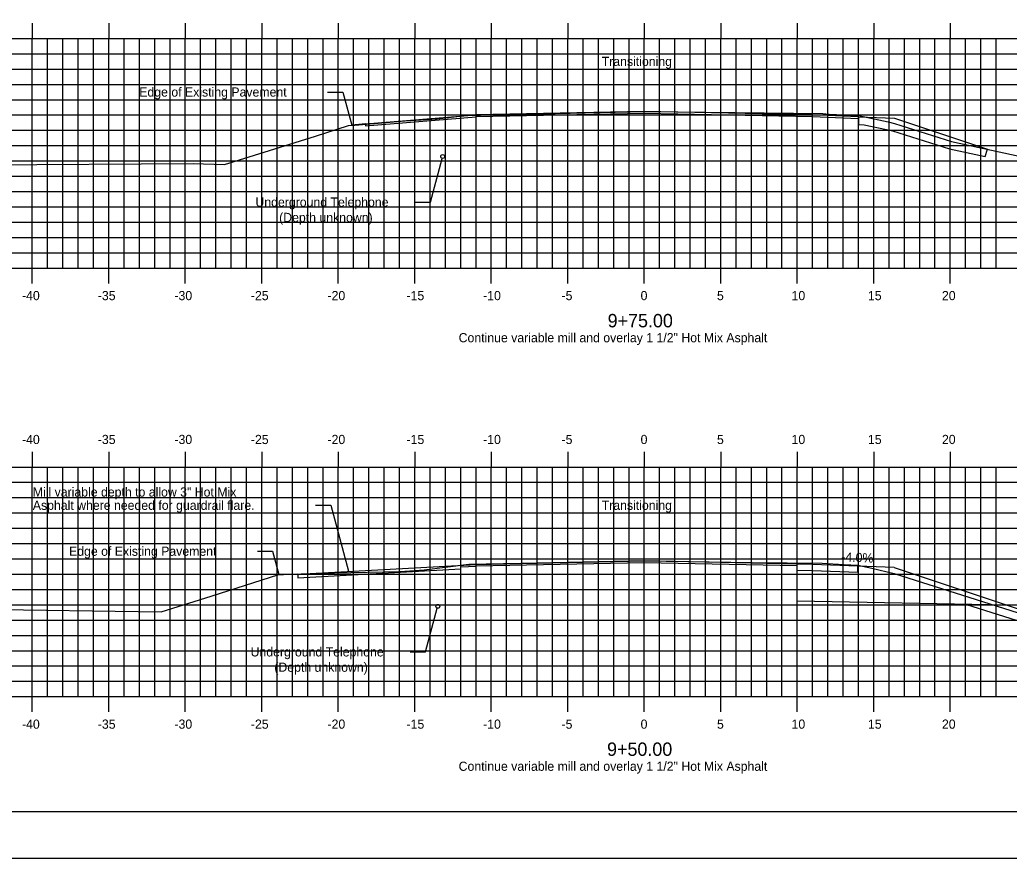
# Model space of a CAD drawing. Extents: x 2194738 to 2195190, y 863888 to 863998.
# Drawn here: x 2194879.4 to 2194944.1, y 863888.4 to 863943.2 of the extents above; entities that cross this region are included whole.
import ezdxf

# ---------------------------------------------------------------- set-up
doc = ezdxf.new("R2010")
doc.units = 0
for name, color, linetype in [('ANNOTATION', 7, 'Continuous'), ('BORDER', 7, 'Continuous'), ('H_V ANNOTATION', 7, 'Continuous'), ('MAJOR', 7, 'Continuous'), ('MINOR', 7, 'Continuous'), ('PLOT BOUNDARY', 7, 'Continuous'), ('S_Roadway_Centerline', 7, 'Continuous'), ('S_Utilities_Pole_Power', 7, 'Continuous'), ('TEMPLATE', 7, 'Continuous')]:
    doc.layers.add(name, color=color, linetype=linetype)

msp = doc.modelspace()

# ---------------------------------------------------------------- linework, layer by layer
at = {"layer": 'ANNOTATION'}
for points in [[(2194899.551, 863938.446), (2194900.551, 863938.446), (2194900.551, 863938.446), (2194901.131, 863936.283)], [(2194905.279, 863931.255), (2194906.279, 863931.255), (2194907.043, 863934.109)], [(2194898.768, 863911.446), (2194899.768, 863911.446), (2194900.923, 863907.133)], [(2194894.964, 863908.446), (2194895.964, 863908.446), (2194895.964, 863908.446), (2194896.37, 863906.93)], [(2194904.963, 863901.869), (2194905.963, 863901.869), (2194906.727, 863904.723)]]:
    msp.add_lwpolyline(points, dxfattribs=at)
at = {"layer": 'BORDER'}
msp.add_lwpolyline([(2194845.256, 863891.446), (2195005.256, 863891.446), (2195005.256, 863996.446), (2194845.256, 863996.446)], close=True, dxfattribs=at)
at = {"layer": 'MAJOR'}
for p, q in [((2194880.256, 863942.948), (2194880.256, 863941.946)), ((2194885.256, 863942.948), (2194885.256, 863941.946)), ((2194890.256, 863942.948), (2194890.256, 863941.946)), ((2194895.256, 863942.948), (2194895.256, 863941.946)), ((2194900.256, 863942.948), (2194900.256, 863941.946)), ((2194905.256, 863942.948), (2194905.256, 863941.946)), ((2194910.256, 863942.948), (2194910.256, 863941.946)), ((2194915.256, 863942.948), (2194915.256, 863941.946)), ((2194920.256, 863942.948), (2194920.256, 863941.946)), ((2194925.256, 863942.948), (2194925.256, 863941.946)), ((2194930.256, 863942.948), (2194930.256, 863941.946)), ((2194935.256, 863942.948), (2194935.256, 863941.946)), ((2194940.256, 863942.948), (2194940.256, 863941.946)), ((2194850.256, 863941.946), (2194990.256, 863941.946)), ((2194880.256, 863926.946), (2194880.256, 863941.946)), ((2194885.256, 863926.946), (2194885.256, 863941.946)), ((2194890.256, 863926.946), (2194890.256, 863941.946)), ((2194895.256, 863926.946), (2194895.256, 863941.946)), ((2194900.256, 863926.946), (2194900.256, 863941.946)), ((2194905.256, 863926.946), (2194905.256, 863941.946)), ((2194910.256, 863926.946), (2194910.256, 863941.946)), ((2194915.256, 863926.946), (2194915.256, 863941.946)), ((2194920.256, 863926.946), (2194920.256, 863941.946)), ((2194925.256, 863926.946), (2194925.256, 863941.946)), ((2194930.256, 863926.946), (2194930.256, 863941.946)), ((2194935.256, 863926.946), (2194935.256, 863941.946)), ((2194940.256, 863926.946), (2194940.256, 863941.946)), ((2194850.256, 863936.946), (2194990.256, 863936.946)), ((2194850.256, 863931.946), (2194990.256, 863931.946)), ((2194850.256, 863926.946), (2194990.256, 863926.946)), ((2194880.256, 863925.944), (2194880.256, 863926.946)), ((2194885.256, 863925.944), (2194885.256, 863926.946)), ((2194890.256, 863925.944), (2194890.256, 863926.946)), ((2194895.256, 863925.944), (2194895.256, 863926.946)), ((2194900.256, 863925.944), (2194900.256, 863926.946)), ((2194905.256, 863925.944), (2194905.256, 863926.946)), ((2194910.256, 863925.944), (2194910.256, 863926.946)), ((2194915.256, 863925.944), (2194915.256, 863926.946)), ((2194920.256, 863925.944), (2194920.256, 863926.946)), ((2194925.256, 863925.944), (2194925.256, 863926.946)), ((2194930.256, 863925.944), (2194930.256, 863926.946)), ((2194935.256, 863925.944), (2194935.256, 863926.946)), ((2194940.256, 863925.944), (2194940.256, 863926.946)), ((2194880.256, 863914.948), (2194880.256, 863913.946)), ((2194885.256, 863914.948), (2194885.256, 863913.946)), ((2194890.256, 863914.948), (2194890.256, 863913.946)), ((2194895.256, 863914.948), (2194895.256, 863913.946)), ((2194900.256, 863914.948), (2194900.256, 863913.946)), ((2194905.256, 863914.948), (2194905.256, 863913.946)), ((2194910.256, 863914.948), (2194910.256, 863913.946)), ((2194915.256, 863914.948), (2194915.256, 863913.946)), ((2194920.256, 863914.948), (2194920.256, 863913.946)), ((2194925.256, 863914.948), (2194925.256, 863913.946)), ((2194930.256, 863914.948), (2194930.256, 863913.946)), ((2194935.256, 863914.948), (2194935.256, 863913.946)), ((2194940.256, 863914.948), (2194940.256, 863913.946)), ((2194850.256, 863913.946), (2194990.256, 863913.946)), ((2194850.256, 863913.946), (2194990.256, 863913.946)), ((2194880.256, 863898.946), (2194880.256, 863913.946)), ((2194885.256, 863898.946), (2194885.256, 863913.946)), ((2194890.256, 863898.946), (2194890.256, 863913.946)), ((2194895.256, 863898.946), (2194895.256, 863913.946)), ((2194900.256, 863898.946), (2194900.256, 863913.946)), ((2194905.256, 863898.946), (2194905.256, 863913.946)), ((2194910.256, 863898.946), (2194910.256, 863913.946)), ((2194915.256, 863898.946), (2194915.256, 863913.946)), ((2194920.256, 863898.946), (2194920.256, 863913.946)), ((2194925.256, 863898.946), (2194925.256, 863913.946)), ((2194930.256, 863898.946), (2194930.256, 863913.946)), ((2194935.256, 863898.946), (2194935.256, 863913.946)), ((2194940.256, 863898.946), (2194940.256, 863913.946)), ((2194850.256, 863908.946), (2194990.256, 863908.946)), ((2194850.256, 863903.946), (2194990.256, 863903.946)), ((2194850.256, 863898.946), (2194990.256, 863898.946)), ((2194880.256, 863897.944), (2194880.256, 863898.946)), ((2194885.256, 863897.944), (2194885.256, 863898.946)), ((2194890.256, 863897.944), (2194890.256, 863898.946)), ((2194895.256, 863897.944), (2194895.256, 863898.946)), ((2194900.256, 863897.944), (2194900.256, 863898.946)), ((2194905.256, 863897.944), (2194905.256, 863898.946)), ((2194910.256, 863897.944), (2194910.256, 863898.946)), ((2194915.256, 863897.944), (2194915.256, 863898.946)), ((2194920.256, 863897.944), (2194920.256, 863898.946)), ((2194925.256, 863897.944), (2194925.256, 863898.946)), ((2194930.256, 863897.944), (2194930.256, 863898.946)), ((2194935.256, 863897.944), (2194935.256, 863898.946)), ((2194940.256, 863897.944), (2194940.256, 863898.946))]:
    msp.add_line(p, q, dxfattribs=at)
at = {"layer": 'MINOR'}
for p, q in [((2194881.256, 863926.946), (2194881.256, 863941.946)), ((2194882.256, 863926.946), (2194882.256, 863941.946)), ((2194883.256, 863926.946), (2194883.256, 863941.946)), ((2194884.256, 863926.946), (2194884.256, 863941.946)), ((2194886.256, 863926.946), (2194886.256, 863941.946)), ((2194887.256, 863926.946), (2194887.256, 863941.946)), ((2194888.256, 863926.946), (2194888.256, 863941.946)), ((2194889.256, 863926.946), (2194889.256, 863941.946)), ((2194891.256, 863926.946), (2194891.256, 863941.946)), ((2194892.256, 863926.946), (2194892.256, 863941.946)), ((2194893.256, 863926.946), (2194893.256, 863941.946)), ((2194894.256, 863926.946), (2194894.256, 863941.946)), ((2194896.256, 863926.946), (2194896.256, 863941.946)), ((2194897.256, 863926.946), (2194897.256, 863941.946)), ((2194898.256, 863926.946), (2194898.256, 863941.946)), ((2194899.256, 863926.946), (2194899.256, 863941.946)), ((2194901.256, 863926.946), (2194901.256, 863941.946)), ((2194902.256, 863926.946), (2194902.256, 863941.946)), ((2194903.256, 863926.946), (2194903.256, 863941.946)), ((2194904.256, 863926.946), (2194904.256, 863941.946)), ((2194906.256, 863926.946), (2194906.256, 863941.946)), ((2194907.256, 863926.946), (2194907.256, 863941.946)), ((2194908.256, 863926.946), (2194908.256, 863941.946)), ((2194909.256, 863926.946), (2194909.256, 863941.946)), ((2194911.256, 863926.946), (2194911.256, 863941.946)), ((2194912.256, 863926.946), (2194912.256, 863941.946)), ((2194913.256, 863926.946), (2194913.256, 863941.946)), ((2194914.256, 863926.946), (2194914.256, 863941.946)), ((2194916.256, 863926.946), (2194916.256, 863941.946)), ((2194917.256, 863926.946), (2194917.256, 863941.946)), ((2194918.256, 863926.946), (2194918.256, 863941.946)), ((2194919.256, 863926.946), (2194919.256, 863941.946)), ((2194921.256, 863926.946), (2194921.256, 863941.946)), ((2194922.256, 863926.946), (2194922.256, 863941.946)), ((2194923.256, 863926.946), (2194923.256, 863941.946)), ((2194924.256, 863926.946), (2194924.256, 863941.946)), ((2194926.256, 863926.946), (2194926.256, 863941.946)), ((2194927.256, 863926.946), (2194927.256, 863941.946)), ((2194928.256, 863926.946), (2194928.256, 863941.946)), ((2194929.256, 863926.946), (2194929.256, 863941.946)), ((2194931.256, 863926.946), (2194931.256, 863941.946)), ((2194932.256, 863926.946), (2194932.256, 863941.946)), ((2194933.256, 863926.946), (2194933.256, 863941.946)), ((2194934.256, 863926.946), (2194934.256, 863941.946)), ((2194936.256, 863926.946), (2194936.256, 863941.946)), ((2194937.256, 863926.946), (2194937.256, 863941.946)), ((2194938.256, 863926.946), (2194938.256, 863941.946)), ((2194939.256, 863926.946), (2194939.256, 863941.946)), ((2194941.256, 863926.946), (2194941.256, 863941.946)), ((2194942.256, 863926.946), (2194942.256, 863941.946)), ((2194943.256, 863926.946), (2194943.256, 863941.946)), ((2194850.256, 863940.946), (2194990.256, 863940.946)), ((2194850.256, 863939.946), (2194990.256, 863939.946)), ((2194850.256, 863938.946), (2194990.256, 863938.946)), ((2194850.256, 863937.946), (2194990.256, 863937.946)), ((2194850.256, 863935.946), (2194990.256, 863935.946)), ((2194850.256, 863934.946), (2194990.256, 863934.946)), ((2194850.256, 863933.946), (2194990.256, 863933.946)), ((2194850.256, 863932.946), (2194990.256, 863932.946)), ((2194850.256, 863930.946), (2194990.256, 863930.946)), ((2194850.256, 863929.946), (2194990.256, 863929.946)), ((2194850.256, 863928.946), (2194990.256, 863928.946)), ((2194850.256, 863927.946), (2194990.256, 863927.946)), ((2194881.256, 863898.946), (2194881.256, 863913.946)), ((2194882.256, 863898.946), (2194882.256, 863913.946)), ((2194883.256, 863898.946), (2194883.256, 863913.946)), ((2194884.256, 863898.946), (2194884.256, 863913.946)), ((2194886.256, 863898.946), (2194886.256, 863913.946)), ((2194887.256, 863898.946), (2194887.256, 863913.946)), ((2194888.256, 863898.946), (2194888.256, 863913.946)), ((2194889.256, 863898.946), (2194889.256, 863913.946)), ((2194891.256, 863898.946), (2194891.256, 863913.946)), ((2194892.256, 863898.946), (2194892.256, 863913.946)), ((2194893.256, 863898.946), (2194893.256, 863913.946)), ((2194894.256, 863898.946), (2194894.256, 863913.946)), ((2194896.256, 863898.946), (2194896.256, 863913.946)), ((2194897.256, 863898.946), (2194897.256, 863913.946)), ((2194898.256, 863898.946), (2194898.256, 863913.946)), ((2194899.256, 863898.946), (2194899.256, 863913.946)), ((2194901.256, 863898.946), (2194901.256, 863913.946)), ((2194902.256, 863898.946), (2194902.256, 863913.946)), ((2194903.256, 863898.946), (2194903.256, 863913.946)), ((2194904.256, 863898.946), (2194904.256, 863913.946)), ((2194906.256, 863898.946), (2194906.256, 863913.946)), ((2194907.256, 863898.946), (2194907.256, 863913.946)), ((2194908.256, 863898.946), (2194908.256, 863913.946)), ((2194909.256, 863898.946), (2194909.256, 863913.946)), ((2194911.256, 863898.946), (2194911.256, 863913.946)), ((2194912.256, 863898.946), (2194912.256, 863913.946)), ((2194913.256, 863898.946), (2194913.256, 863913.946)), ((2194914.256, 863898.946), (2194914.256, 863913.946)), ((2194916.256, 863898.946), (2194916.256, 863913.946)), ((2194917.256, 863898.946), (2194917.256, 863913.946)), ((2194918.256, 863898.946), (2194918.256, 863913.946)), ((2194919.256, 863898.946), (2194919.256, 863913.946)), ((2194921.256, 863898.946), (2194921.256, 863913.946)), ((2194922.256, 863898.946), (2194922.256, 863913.946)), ((2194923.256, 863898.946), (2194923.256, 863913.946)), ((2194924.256, 863898.946), (2194924.256, 863913.946)), ((2194926.256, 863898.946), (2194926.256, 863913.946)), ((2194927.256, 863898.946), (2194927.256, 863913.946)), ((2194928.256, 863898.946), (2194928.256, 863913.946)), ((2194929.256, 863898.946), (2194929.256, 863913.946)), ((2194931.256, 863898.946), (2194931.256, 863913.946)), ((2194932.256, 863898.946), (2194932.256, 863913.946)), ((2194933.256, 863898.946), (2194933.256, 863913.946)), ((2194934.256, 863898.946), (2194934.256, 863913.946)), ((2194936.256, 863898.946), (2194936.256, 863913.946)), ((2194937.256, 863898.946), (2194937.256, 863913.946)), ((2194938.256, 863898.946), (2194938.256, 863913.946)), ((2194939.256, 863898.946), (2194939.256, 863913.946)), ((2194941.256, 863898.946), (2194941.256, 863913.946)), ((2194942.256, 863898.946), (2194942.256, 863913.946)), ((2194943.256, 863898.946), (2194943.256, 863913.946)), ((2194850.256, 863912.946), (2194990.256, 863912.946)), ((2194850.256, 863911.946), (2194990.256, 863911.946)), ((2194850.256, 863910.946), (2194990.256, 863910.946)), ((2194850.256, 863909.946), (2194990.256, 863909.946)), ((2194850.256, 863907.946), (2194990.256, 863907.946)), ((2194850.256, 863906.946), (2194990.256, 863906.946)), ((2194850.256, 863905.946), (2194990.256, 863905.946)), ((2194850.256, 863904.946), (2194990.256, 863904.946)), ((2194850.256, 863902.946), (2194990.256, 863902.946)), ((2194850.256, 863901.946), (2194990.256, 863901.946)), ((2194850.256, 863900.946), (2194990.256, 863900.946)), ((2194850.256, 863899.946), (2194990.256, 863899.946))]:
    msp.add_line(p, q, dxfattribs=at)
at = {"layer": 'PLOT BOUNDARY'}
msp.add_lwpolyline([(2194837.163, 863888.387), (2195007.163, 863888.387), (2195007.163, 863998.387), (2194837.163, 863998.387)], close=True, dxfattribs=at)
at = {"layer": 'S_Roadway_Centerline'}
for points in [[(2194850.256, 863932.472), (2194857.621, 863933.113), (2194863.174, 863933.605), (2194863.505, 863933.61), (2194890.775, 863933.767), (2194892.823, 863933.711), (2194893.448, 863933.904), (2194898.762, 863935.554), (2194900.923, 863936.26), (2194901.131, 863936.283), (2194901.34, 863936.29), (2194904.626, 863936.557), (2194906.71, 863936.685), (2194908.573, 863936.911), (2194918.35, 863937.137), (2194920.338, 863937.169), (2194922.335, 863937.142), (2194931.931, 863937.033), (2194932.342, 863937.008), (2194934.265, 863936.902), (2194936.186, 863936.495), (2194936.603, 863936.399), (2194940.327, 863935.219), (2194952.094, 863932.661)], [(2194850.256, 863903.946), (2194862.163, 863904.928), (2194876.641, 863904.659), (2194888.683, 863904.484), (2194891.949, 863905.503), (2194896.37, 863906.93), (2194900.004, 863907.039), (2194904.289, 863907.129), (2194905.874, 863907.236), (2194908.794, 863907.591), (2194913.318, 863907.695), (2194920.296, 863907.807), (2194927.306, 863907.711), (2194931.88, 863907.66), (2194933.306, 863907.572), (2194934.219, 863907.522), (2194935.131, 863907.329), (2194936.586, 863906.993), (2194949.583, 863902.874), (2194953.328, 863902.06), (2194962.598, 863900.741), (2194971.313, 863899.617), (2194975.97, 863899.247), (2194990.256, 863899.22)]]:
    msp.add_lwpolyline(points, dxfattribs=at)
at = {"layer": 'S_Utilities_Pole_Power'}
for centre in [(2194907.076, 863934.229), (2194906.76, 863904.844)]:
    msp.add_circle(centre, 0.125, dxfattribs=at)
at = {"layer": 'TEMPLATE'}
for p, q in [((2194902.03, 863936.357), (2194909.256, 863936.948)), ((2194909.256, 863936.948), (2194920.256, 863937.168)), ((2194920.256, 863937.168), (2194909.256, 863936.948)), ((2194920.256, 863937.043), (2194909.256, 863936.823)), ((2194931.256, 863936.948), (2194920.256, 863937.168)), ((2194931.256, 863936.823), (2194920.256, 863937.043)), ((2194934.265, 863936.827), (2194931.256, 863936.948)), ((2194934.265, 863936.702), (2194931.256, 863936.823)), ((2194934.265, 863936.827), (2194934.265, 863936.702)), ((2194934.265, 863936.827), (2194936.603, 863936.734)), ((2194902.03, 863936.357), (2194901.131, 863936.283)), ((2194936.603, 863936.734), (2194942.686, 863934.706)), ((2194909.256, 863907.587), (2194920.256, 863907.807)), ((2194920.256, 863907.807), (2194909.256, 863907.587)), ((2194920.256, 863907.682), (2194909.256, 863907.462)), ((2194931.256, 863907.587), (2194920.256, 863907.807)), ((2194930.256, 863907.482), (2194920.256, 863907.682)), ((2194930.256, 863905.191), (2194930.256, 863907.482)), ((2194931.256, 863907.171), (2194930.256, 863907.191)), ((2194936.586, 863907.374), (2194931.256, 863907.587)), ((2194934.219, 863907.052), (2194931.256, 863907.171)), ((2194934.219, 863907.052), (2194934.219, 863907.469)), ((2194897.605, 863906.952), (2194896.199, 863906.875)), ((2194943.958, 863904.917), (2194930.256, 863905.191))]:
    msp.add_line(p, q, dxfattribs=at)
for points in [[(2194902.03, 863936.357), (2194902.03, 863936.232), (2194909.256, 863936.823)], [(2194934.265, 863936.702), (2194934.265, 863936.327), (2194934.636, 863936.312)], [(2194934.636, 863936.312), (2194936.078, 863936.007), (2194936.471, 863935.916), (2194940.199, 863934.735), (2194942.527, 863934.229)], [(2194942.527, 863934.229), (2194942.686, 863934.706)], [(2194897.605, 863906.952), (2194909.256, 863907.587)], [(2194897.605, 863906.952), (2194897.605, 863906.701), (2194908.256, 863907.297), (2194908.256, 863907.422)], [(2194908.256, 863907.422), (2194909.256, 863907.462)], [(2194936.586, 863907.374), (2194951.028, 863902.56)], [(2194941.316, 863904.97), (2194949.454, 863902.391), (2194950.921, 863902.072)]]:
    msp.add_lwpolyline(points, dxfattribs=at)

# ---------------------------------------------------------------- texts
at = {"layer": 'ANNOTATION'}
for s, p in [('Transitioning', (2194917.472, 863940.146)), ('Edge of Existing Pavement', (2194887.245, 863938.146)), ('Underground Telephone', (2194894.839, 863930.955)), ('(Depth unknown)', (2194896.389, 863929.953)), ('Continue variable mill and overlay 1 1/2" Hot Mix Asphalt', (2194908.121, 863922.096)), ('Mill variable depth to allow 3" Hot Mix', (2194880.287, 863912.013)), ('Asphalt where needed for guardrail flare.', (2194880.287, 863911.146)), ('Transitioning', (2194917.472, 863911.146)), ('Edge of Existing Pavement', (2194882.657, 863908.146)), ('Underground Telephone', (2194894.523, 863901.569)), ('(Depth unknown)', (2194896.073, 863900.567)), ('Continue variable mill and overlay 1 1/2" Hot Mix Asphalt', (2194908.121, 863894.096))]:
    msp.add_text(s, height=0.6, dxfattribs=at).set_placement(p)
msp.add_text('-4.0%', height=0.6, rotation=357.70939, dxfattribs=at).set_placement((2194933.122, 863907.78))
at = {"layer": 'H_V ANNOTATION'}
for s, height, p in [('-40', 0.6, (2194879.582, 863924.846)), ('-35', 0.6, (2194884.536, 863924.846)), ('-30', 0.6, (2194889.544, 863924.846)), ('-25', 0.6, (2194894.541, 863924.846)), ('-20', 0.6, (2194899.549, 863924.846)), ('-15', 0.6, (2194904.713, 863924.846)), ('-10', 0.6, (2194909.721, 863924.846)), ('-5', 0.6, (2194914.846, 863924.846)), ('0', 0.6, (2194920.015, 863924.846)), ('5', 0.6, (2194925.007, 863924.846)), ('10', 0.6, (2194929.881, 863924.846)), ('15', 0.6, (2194934.873, 863924.846)), ('20', 0.6, (2194939.71, 863924.846)), ('9+75.00', 0.875, (2194917.86, 863923.071)), ('-40', 0.6, (2194879.582, 863915.446)), ('-35', 0.6, (2194884.536, 863915.446)), ('-30', 0.6, (2194889.544, 863915.446)), ('-25', 0.6, (2194894.541, 863915.446)), ('-20', 0.6, (2194899.549, 863915.446)), ('-15', 0.6, (2194904.713, 863915.446)), ('-10', 0.6, (2194909.721, 863915.446)), ('-5', 0.6, (2194914.846, 863915.446)), ('0', 0.6, (2194920.015, 863915.446)), ('5', 0.6, (2194925.007, 863915.446)), ('10', 0.6, (2194929.881, 863915.446)), ('15', 0.6, (2194934.873, 863915.446)), ('20', 0.6, (2194939.71, 863915.446)), ('-40', 0.6, (2194879.582, 863896.846)), ('-35', 0.6, (2194884.536, 863896.846)), ('-30', 0.6, (2194889.544, 863896.846)), ('-25', 0.6, (2194894.541, 863896.846)), ('-20', 0.6, (2194899.549, 863896.846)), ('-15', 0.6, (2194904.713, 863896.846)), ('-10', 0.6, (2194909.721, 863896.846)), ('-5', 0.6, (2194914.846, 863896.846)), ('0', 0.6, (2194920.015, 863896.846)), ('5', 0.6, (2194925.007, 863896.846)), ('10', 0.6, (2194929.881, 863896.846)), ('15', 0.6, (2194934.873, 863896.846)), ('20', 0.6, (2194939.71, 863896.846)), ('9+50.00', 0.875, (2194917.821, 863895.071))]:
    msp.add_text(s, height=height, dxfattribs=at).set_placement(p)

doc.saveas('drawing.dxf')
